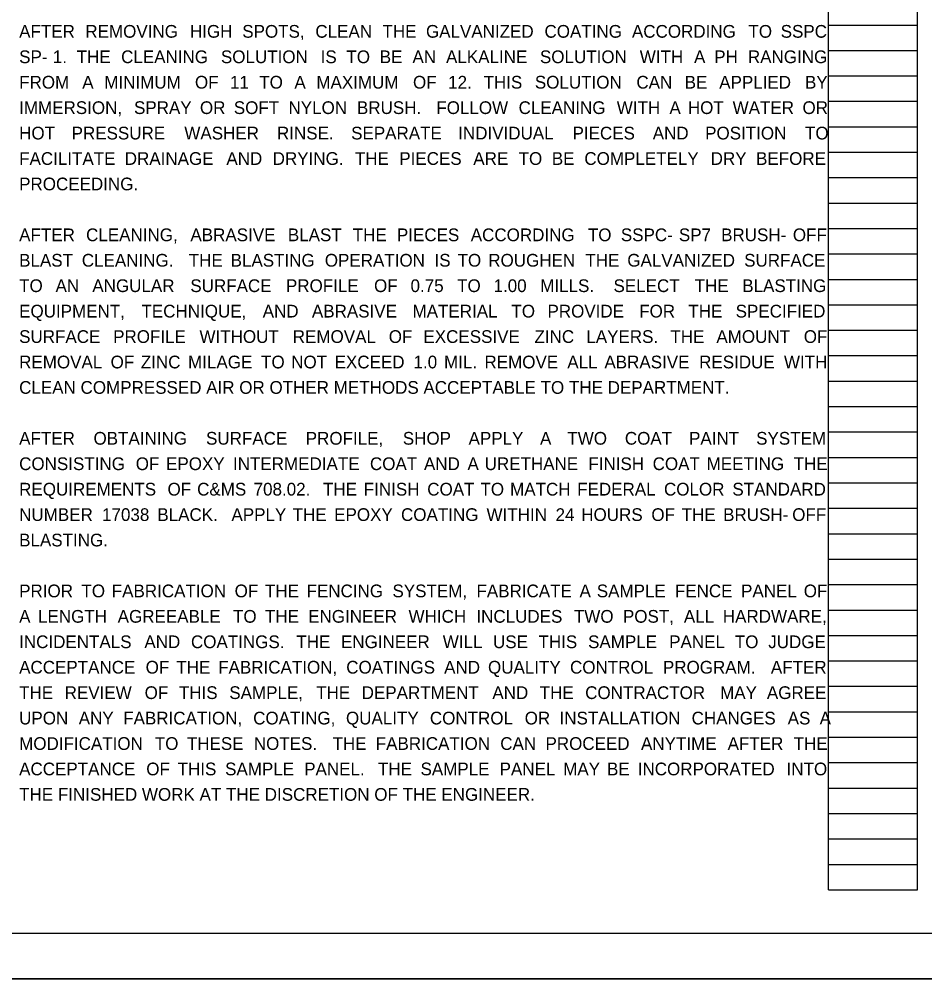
# Model space of a CAD drawing. Extents: x 0 to 34, y 0 to 22.
# Drawn here: x 12.29 to 22.27, y 0 to 10.56 of the extents above; entities that cross this region are included whole.
import ezdxf

# ---------------------------------------------------------------- set-up
doc = ezdxf.new("R2010")
doc.units = 0
for name, color, linetype in [('SC_Scratch1', 7, 'Continuous'), ('SH_Border', 7, 'Continuous'), ('SH_Cut_Line', 7, 'Continuous'), ('SH_Text', 7, 'Continuous')]:
    doc.layers.add(name, color=color, linetype=linetype)

msp = doc.modelspace()

# ---------------------------------------------------------------- linework, layer by layer
at = {"layer": 'SC_Scratch1'}
for p, q in [((21.207, 0.98), (21.207, 21.14)), ((22.187, 0.98), (22.187, 21.14)), ((21.207, 10.5), (22.187, 10.5)), ((21.207, 10.22), (22.187, 10.22)), ((21.207, 9.94), (22.187, 9.94)), ((21.207, 9.66), (22.187, 9.66)), ((21.207, 9.38), (22.187, 9.38)), ((21.207, 9.1), (22.187, 9.1)), ((21.207, 8.82), (22.187, 8.82)), ((21.207, 8.54), (22.187, 8.54)), ((21.207, 8.26), (22.187, 8.26)), ((21.207, 7.98), (22.187, 7.98)), ((21.207, 7.7), (22.187, 7.7)), ((21.207, 7.42), (22.187, 7.42)), ((21.207, 7.14), (22.187, 7.14)), ((21.207, 6.86), (22.187, 6.86)), ((21.207, 6.58), (22.187, 6.58)), ((21.207, 6.3), (22.187, 6.3)), ((21.207, 6.02), (22.187, 6.02)), ((21.207, 5.74), (22.187, 5.74)), ((21.207, 5.46), (22.187, 5.46)), ((21.207, 5.18), (22.187, 5.18)), ((21.207, 4.9), (22.187, 4.9)), ((21.207, 4.62), (22.187, 4.62)), ((21.207, 4.34), (22.187, 4.34)), ((21.207, 4.06), (22.187, 4.06)), ((21.207, 3.78), (22.187, 3.78)), ((21.207, 3.5), (22.187, 3.5)), ((21.207, 3.22), (22.187, 3.22)), ((21.207, 2.94), (22.187, 2.94)), ((21.207, 2.66), (22.187, 2.66)), ((21.207, 2.38), (22.187, 2.38)), ((21.207, 2.1), (22.187, 2.1)), ((21.207, 1.82), (22.187, 1.82)), ((21.207, 1.54), (22.187, 1.54)), ((21.207, 1.26), (22.187, 1.26)), ((21.207, 0.98), (22.187, 0.98))]:
    msp.add_line(p, q, dxfattribs=at)
msp.add_lwpolyline([(0, 22), (34, 22), (34, 0), (0, 0)], close=True, dxfattribs=at)
at = {"layer": 'SH_Border'}
msp.add_lwpolyline([(1.5, 21.5), (33.5, 21.5), (33.5, 0.5), (1.5, 0.5)], close=True, dxfattribs=at)
at = {"layer": 'SH_Cut_Line'}
msp.add_lwpolyline([(0, 0), (34, 0), (34, 22), (0, 22)], close=True, dxfattribs=at)

# ---------------------------------------------------------------- texts
at = {"layer": 'SH_Text'}
for s, p in [('AFTER ', (12.293, 10.36)), ('REMOVING ', (13.022, 10.36)), ('HIGH ', (14.174, 10.36)), ('SPOTS, ', (14.75, 10.36)), ('CLEAN ', (15.555, 10.36)), ('THE ', (16.294, 10.36)), ('GALVANIZED ', (16.773, 10.36)), ('COATING ', (18.078, 10.36)), ('ACCORDING ', (19.041, 10.36)), ('TO ', (20.324, 10.36)), ('SSPC ', (20.679, 10.36)), ('SP-', (12.293, 10.08)), ('1. ', (12.664, 10.08)), ('THE ', (12.926, 10.08)), ('CLEANING ', (13.416, 10.08)), ('SOLUTION ', (14.515, 10.08)), ('IS ', (15.613, 10.08)), ('TO ', (15.897, 10.08)), ('BE ', (16.264, 10.08)), ('AN ', (16.624, 10.08)), ('ALKALINE ', (16.994, 10.08)), ('SOLUTION ', (18.028, 10.08)), ('WITH ', (19.127, 10.08)), ('A ', (19.725, 10.08)), ('PH ', (19.947, 10.08)), ('RANGING ', (20.318, 10.08)), ('FROM ', (12.293, 9.8)), ('A ', (12.988, 9.8)), ('MINIMUM ', (13.23, 9.8)), ('OF ', (14.229, 9.8)), ('11 ', (14.615, 9.8)), ('TO ', (14.937, 9.8)), ('A ', (15.324, 9.8)), ('MAXIMUM ', (15.566, 9.8)), ('OF ', (16.63, 9.8)), ('12. ', (17.017, 9.8)), ('THIS ', (17.407, 9.8)), ('SOLUTION ', (17.972, 9.8)), ('CAN ', (19.09, 9.8)), ('BE ', (19.622, 9.8)), ('APPLIED ', (20.002, 9.8)), ('BY ', (20.947, 9.8)), ('IMMERSION, ', (12.293, 9.52)), ('SPRAY ', (13.558, 9.52)), ('OR ', (14.284, 9.52)), ('SOFT ', (14.657, 9.52)), ('NYLON ', (15.259, 9.52)), ('BRUSH.  ', (16.013, 9.52)), ('FOLLOW ', (16.887, 9.52)), ('CLEANING ', (17.793, 9.52)), ('WITH ', (18.874, 9.52)), ('A ', (19.454, 9.52)), ('HOT ', (19.657, 9.52)), ('WATER ', (20.15, 9.52)), ('OR ', (20.919, 9.52)), ('HOT ', (12.293, 9.24)), ('PRESSURE ', (12.871, 9.24)), ('WASHER ', (14.112, 9.24)), ('RINSE. ', (15.132, 9.24)), ('SEPARATE ', (15.949, 9.24)), ('INDIVIDUAL ', (17.128, 9.24)), ('PIECES ', (18.387, 9.24)), ('AND ', (19.27, 9.24)), ('POSITION ', (19.847, 9.24)), ('TO ', (20.947, 9.24)), ('FACILITATE ', (12.293, 8.96)), ('DRAINAGE ', (13.456, 8.96)), ('AND ', (14.575, 8.96)), ('DRYING. ', (15.085, 8.96)), ('THE ', (15.99, 8.96)), ('PIECES ', (16.479, 8.96)), ('ARE ', (17.294, 8.96)), ('TO ', (17.793, 8.96)), ('BE ', (18.159, 8.96)), ('COMPLETELY ', (18.517, 8.96)), ('DRY ', (19.908, 8.96)), ('BEFORE ', (20.408, 8.96)), ('PROCEEDING. ', (12.293, 8.68)), ('AFTER ', (12.293, 8.12)), ('CLEANING, ', (13.03, 8.12)), ('ABRASIVE ', (14.179, 8.12)), ('BLAST ', (15.252, 8.12)), ('THE ', (15.967, 8.12)), ('PIECES ', (16.453, 8.12)), ('ACCORDING ', (17.266, 8.12)), ('TO ', (18.556, 8.12)), ('SSPC-', (18.919, 8.12)), ('SP7 ', (19.558, 8.12)), ('BRUSH-', (20.023, 8.12)), ('OFF ', (20.813, 8.12)), ('BLAST ', (12.293, 7.84)), ('CLEANING.  ', (12.983, 7.84)), ('THE ', (14.161, 7.84)), ('BLASTING ', (14.622, 7.84)), ('OPERATION ', (15.659, 7.84)), ('IS ', (16.867, 7.84)), ('TO ', (17.121, 7.84)), ('ROUGHEN ', (17.459, 7.84)), ('THE ', (18.529, 7.84)), ('GALVANIZED ', (18.99, 7.84)), ('SURFACE ', (20.277, 7.84)), ('TO ', (12.293, 7.56)), ('AN ', (12.694, 7.56)), ('ANGULAR ', (13.099, 7.56)), ('SURFACE ', (14.178, 7.56)), ('PROFILE ', (15.231, 7.56)), ('OF ', (16.201, 7.56)), ('0.75 ', (16.603, 7.56)), ('TO ', (17.116, 7.56)), ('1.00 ', (17.517, 7.56)), ('MILLS.  ', (18.031, 7.56)), ('SELECT ', (18.838, 7.56)), ('THE ', (19.732, 7.56)), ('BLASTING ', (20.256, 7.56)), ('EQUIPMENT, ', (12.293, 7.28)), ('TECHNIQUE, ', (13.64, 7.28)), ('AND ', (14.975, 7.28)), ('ABRASIVE ', (15.517, 7.28)), ('MATERIAL ', (16.625, 7.28)), ('TO ', (17.714, 7.28)), ('PROVIDE ', (18.111, 7.28)), ('FOR ', (19.121, 7.28)), ('THE ', (19.663, 7.28)), ('SPECIFIED ', (20.183, 7.28)), ('SURFACE ', (12.293, 7)), ('PROFILE ', (13.328, 7)), ('WITHOUT ', (14.279, 7)), ('REMOVAL ', (15.306, 7)), ('OF ', (16.363, 7)), ('EXCESSIVE ', (16.745, 7)), ('ZINC ', (17.968, 7)), ('LAYERS. ', (18.539, 7)), ('THE ', (19.465, 7)), ('AMOUNT ', (19.971, 7)), ('OF ', (20.933, 7)), ('REMOVAL ', (12.293, 6.72)), ('OF ', (13.3, 6.72)), ('ZINC ', (13.633, 6.72)), ('MILAGE ', (14.153, 6.72)), ('TO ', (14.957, 6.72)), ('NOT ', (15.289, 6.72)), ('EXCEED ', (15.767, 6.72)), ('1.0 ', (16.636, 6.72)), ('MIL. ', (16.972, 6.72)), ('REMOVE ', (17.417, 6.72)), ('ALL ', (18.329, 6.72)), ('ABRASIVE ', (18.738, 6.72)), ('RESIDUE ', (19.781, 6.72)), ('WITH ', (20.715, 6.72)), ('CLEAN COMPRESSED AIR OR OTHER METHODS ACCEPTABLE TO THE DEPARTMENT.', (12.293, 6.44)), ('OBTAINING ', (13.112, 5.88)), ('SURFACE ', (14.351, 5.88)), ('PROFILE, ', (15.449, 5.88)), ('SHOP ', (16.518, 5.88)), ('TWO ', (18.33, 5.88)), ('COAT ', (18.963, 5.88)), ('SYSTEM ', (20.409, 5.88)), ('AFTER ', (12.293, 5.88)), ('APPLY ', (17.242, 5.88)), ('A ', (18.029, 5.88)), ('PAINT ', (19.67, 5.88)), ('CONSISTING ', (12.293, 5.6)), ('OF ', (13.577, 5.6)), ('EPOXY ', (13.911, 5.6)), ('INTERMEDIATE ', (14.648, 5.6)), ('COAT ', (16.156, 5.6)), ('AND ', (16.751, 5.6)), ('A ', (17.23, 5.6)), ('URETHANE ', (17.419, 5.6)), ('FINISH ', (18.561, 5.6)), ('COAT ', (19.269, 5.6)), ('MEETING ', (19.864, 5.6)), ('THE ', (20.821, 5.6)), ('REQUIREMENTS ', (12.293, 5.32)), ('OF ', (13.927, 5.32)), ('C&MS ', (14.253, 5.32)), ('708.02.  ', (14.875, 5.32)), ('THE ', (15.639, 5.32)), ('FINISH ', (16.088, 5.32)), ('COAT ', (16.787, 5.32)), ('TO ', (17.373, 5.32)), ('MATCH ', (17.699, 5.32)), ('FEDERAL ', (18.438, 5.32)), ('COLOR ', (19.394, 5.32)), ('STANDARD  ', (20.147, 5.32)), ('NUMBER ', (12.293, 5.04)), ('17038 ', (13.206, 5.04)), ('BLACK.  ', (13.815, 5.04)), ('APPLY ', (14.631, 5.04)), ('THE ', (15.305, 5.04)), ('EPOXY ', (15.762, 5.04)), ('COATING ', (16.498, 5.04)), ('WITHIN ', (17.44, 5.04)), ('24 ', (18.2, 5.04)), ('HOURS ', (18.483, 5.04)), ('OF ', (19.255, 5.04)), ('THE ', (19.588, 5.04)), ('BRUSH-', (20.045, 5.04)), ('OFF ', (20.806, 5.04)), ('BLASTING. ', (12.293, 4.76)), ('PRIOR ', (12.293, 4.2)), ('TO ', (12.979, 4.2)), ('FABRICATION ', (13.313, 4.2)), ('OF ', (14.666, 4.2)), ('THE ', (15, 4.2)), ('FENCING ', (15.458, 4.2)), ('SYSTEM, ', (16.404, 4.2)), ('FABRICATE ', (17.329, 4.2)), ('A ', (18.464, 4.2)), ('SAMPLE ', (18.654, 4.2)), ('FENCE ', (19.514, 4.2)), ('PANEL ', (20.243, 4.2)), ('OF ', (20.933, 4.2)), ('A ', (12.293, 3.92)), ('LENGTH ', (12.501, 3.92)), ('AGREEABLE ', (13.378, 3.92)), ('TO ', (14.648, 3.92)), ('THE ', (15, 3.92)), ('ENGINEER ', (15.476, 3.92)), ('WHICH ', (16.581, 3.92)), ('INCLUDES ', (17.328, 3.92)), ('TWO ', (18.402, 3.92)), ('POST, ', (18.942, 3.92)), ('ALL ', (19.613, 3.92)), ('HARDWARE, ', (20.042, 3.92)), ('INCIDENTALS ', (12.293, 3.64)), ('AND ', (13.672, 3.64)), ('COATINGS. ', (14.185, 3.64)), ('THE ', (15.346, 3.64)), ('ENGINEER ', (15.837, 3.64)), ('WILL ', (16.958, 3.64)), ('USE ', (17.511, 3.64)), ('THIS ', (18.012, 3.64)), ('SAMPLE ', (18.558, 3.64)), ('PANEL ', (19.451, 3.64)), ('TO ', (20.174, 3.64)), ('JUDGE ', (20.542, 3.64)), ('ACCEPTANCE ', (12.293, 3.36)), ('OF ', (13.686, 3.36)), ('THE ', (14.024, 3.36)), ('FABRICATION, ', (14.485, 3.36)), ('COATINGS ', (15.895, 3.36)), ('AND ', (16.973, 3.36)), ('QUALITY ', (17.456, 3.36)), ('CONTROL ', (18.359, 3.36)), ('PROGRAM.  ', (19.382, 3.36)), ('AFTER ', (20.571, 3.36)), ('THE ', (12.293, 3.08)), ('REVIEW ', (12.794, 3.08)), ('OF ', (13.675, 3.08)), ('THIS ', (14.052, 3.08)), ('SAMPLE, ', (14.607, 3.08)), ('THE ', (15.564, 3.08)), ('DEPARTMENT ', (16.065, 3.08)), ('AND ', (17.504, 3.08)), ('THE ', (18.026, 3.08)), ('CONTRACTOR ', (18.526, 3.08)), ('MAY ', (20.012, 3.08)), ('AGREE ', (20.527, 3.08)), ('UPON ', (12.293, 2.8)), ('ANY ', (12.949, 2.8)), ('FABRICATION, ', (13.439, 2.8)), ('COATING, ', (14.87, 2.8)), ('QUALITY ', (15.892, 2.8)), ('CONTROL ', (16.816, 2.8)), ('OR ', (17.86, 2.8)), ('INSTALLATION ', (18.244, 2.8)), ('CHANGES ', (19.698, 2.8)), ('AS ', (20.756, 2.8)), ('A ', (21.108, 2.8)), ('MODIFICATION ', (12.293, 2.52)), ('TO ', (13.787, 2.52)), ('THESE ', (14.14, 2.52)), ('NOTES.  ', (14.877, 2.52)), ('THE ', (15.744, 2.52)), ('FABRICATION ', (16.22, 2.52)), ('CAN ', (17.591, 2.52)), ('PROCEED ', (18.089, 2.52)), ('ANYTIME ', (19.141, 2.52)), ('AFTER ', (20.095, 2.52)), ('THE ', (20.821, 2.52)), ('ACCEPTANCE ', (12.293, 2.24)), ('OF ', (13.693, 2.24)), ('THIS ', (14.038, 2.24)), ('SAMPLE ', (14.561, 2.24)), ('PANEL.  ', (15.432, 2.24)), ('THE ', (16.244, 2.24)), ('SAMPLE ', (16.713, 2.24)), ('PANEL ', (17.584, 2.24)), ('MAY ', (18.284, 2.24)), ('BE ', (18.767, 2.24)), ('INCORPORATED ', (19.105, 2.24)), ('INTO ', (20.744, 2.24)), ('THE FINISHED WORK AT THE DISCRETION OF THE ENGINEER.', (12.293, 1.96))]:
    msp.add_text(s, height=0.14, dxfattribs=at).set_placement(p)

doc.saveas('drawing.dxf')
